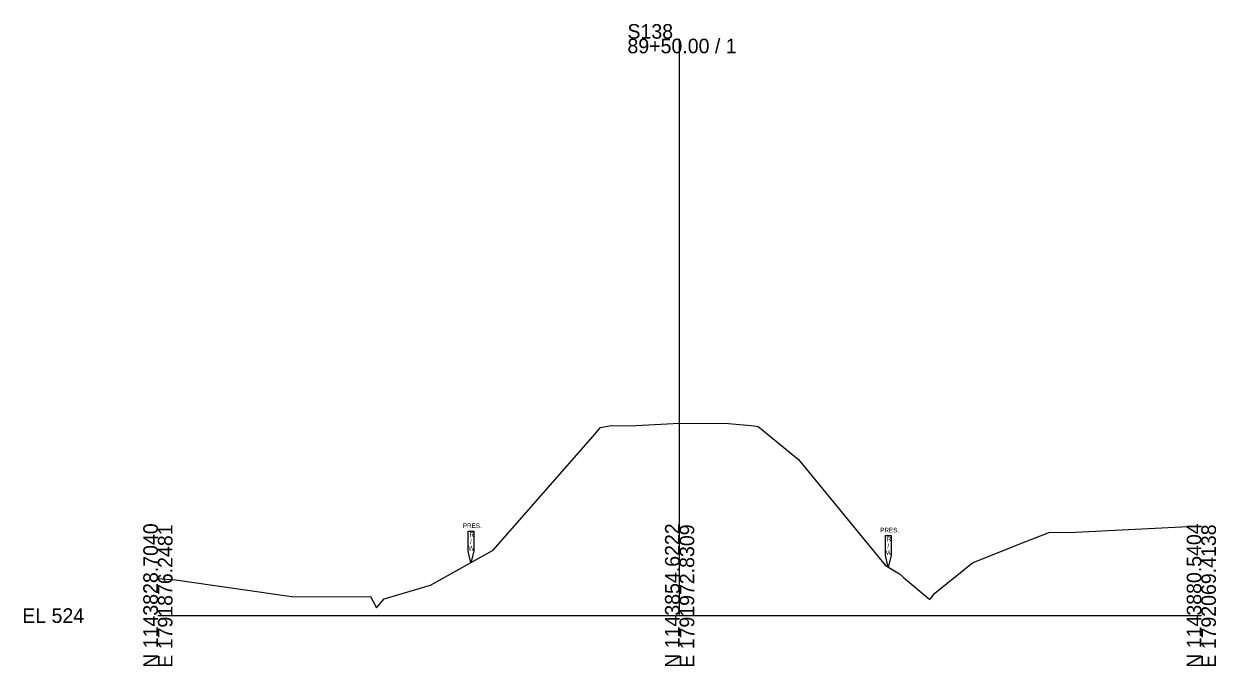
# Model space of a CAD drawing. Extents: x -26 to 1203, y -10 to 19606.
# Drawn here: x -25.7 to 202.8, y 18990.3 to 19113.5 of the extents above; entities that cross this region are included whole.
import ezdxf

# ---------------------------------------------------------------- set-up
doc = ezdxf.new("R2010")
doc.units = 0
for name, color, linetype in [('RD_EX_Driveway', 7, 'Continuous'), ('RD_GPK_XS_Cell', 7, 'Continuous'), ('RD_XS_ExGround', 7, 'Continuous'), ('RD_XS_ExRW', 7, 'Continuous')]:
    doc.layers.add(name, color=color, linetype=linetype)

msp = doc.modelspace()

# ---------------------------------------------------------------- linework, layer by layer
at = {"layer": 'RD_GPK_XS_Cell'}
for p, q in [((100, 19000), (100, 19110.62)), ((0, 19000), (100, 19000)), ((100, 19000), (200, 19000))]:
    msp.add_line(p, q, dxfattribs=at)
at = {"layer": 'RD_XS_ExGround'}
msp.add_lwpolyline([(0, 19007.13), (3.37, 19006.84), (26.08, 19003.61), (40.78, 19003.64), (41.9, 19001.46), (43.39, 19003.21), (52.27, 19005.82), (64.24, 19012.53), (83.01, 19033.91), (84.83, 19036.07), (86.89, 19036.42), (90.49, 19036.38), (100, 19036.87), (109.38, 19036.85), (113.7, 19036.47), (115.06, 19036.28), (122.76, 19029.95), (139.37, 19009.7), (139.91, 19009.37), (142.13, 19007.99), (142.93, 19007.33), (147.93, 19003.1), (148.94, 19004.33), (156.12, 19010.12), (165.86, 19014.01), (167.71, 19014.74), (170.95, 19015.97), (174.58, 19015.91), (200, 19017.24)], dxfattribs=at)
at = {"layer": 'RD_XS_ExRW'}
for points in [[(59.45, 19016.17), (60.55, 19016.17), (60.55, 19012.34), (60, 19010.15), (59.45, 19012.34)], [(139.45, 19015.33), (140.55, 19015.33), (140.55, 19011.5), (140, 19009.31), (139.45, 19011.5)]]:
    msp.add_lwpolyline(points, close=True, dxfattribs=at)

# ---------------------------------------------------------------- texts
at = {"layer": 'RD_EX_Driveway'}
msp.add_text('542.44', height=0.0975, rotation=90, dxfattribs=at).set_placement((100.1, 19036.87))
at = {"layer": 'RD_GPK_XS_Cell'}
for s, p in [('S138', (90, 19110.62)), ('89+50.00 / 1', (90, 19107.82)), ('EL 524', (-26, 18998.6))]:
    msp.add_text(s, height=2.8, dxfattribs=at).set_placement(p)
for s, p in [('N 1143828.7040', (0, 18990)), ('E 1791876.2481', (2.8, 18990)), ('N 1143854.6222', (100, 18990)), ('E 1791972.8309', (102.8, 18990)), ('N 1143880.5404', (200, 18990)), ('E 1792069.4138', (202.8, 18990))]:
    msp.add_text(s, height=2.8, rotation=90, dxfattribs=at).set_placement(p)
at = {"layer": 'RD_XS_ExRW'}
for s, p in [('PRES.', (58.45, 19016.8)), ('PRES.', (138.45, 19015.96)), ('R', (59.71, 19015.08)), ('/', (59.83, 19013.77)), ('R', (139.71, 19014.24)), ('W', (59.53, 19012.45)), ('W', (139.53, 19011.61)), ('/', (139.83, 19012.93))]:
    msp.add_text(s, height=0.875, dxfattribs=at).set_placement(p)

doc.saveas('drawing.dxf')
